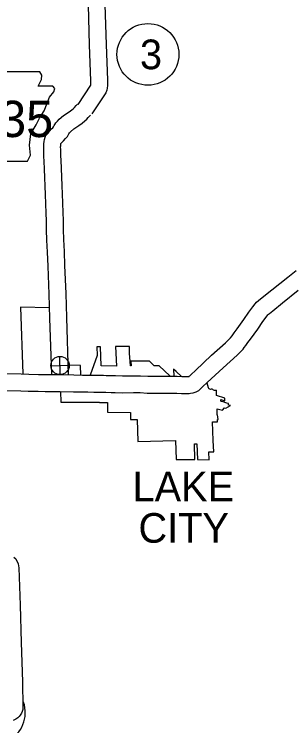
# Model space of a CAD drawing. Extents: x 1671357 to 13005564, y 567358 to 14261451.
# Drawn here: x 12758290.19 to 12758290.727, y 14259953.097 to 14259954.477 of the extents above; entities that cross this region are included whole.
import ezdxf

# ---------------------------------------------------------------- set-up
doc = ezdxf.new("R2010")
doc.units = 0
for name, color, linetype in [('10', 7, 'Continuous'), ('21', 7, 'Continuous'), ('24', 7, 'Continuous'), ('40', 7, 'Continuous'), ('6', 7, 'Continuous')]:
    doc.layers.add(name, color=color, linetype=linetype)

msp = doc.modelspace()

# ---------------------------------------------------------------- linework, layer by layer
at = {"layer": '10'}
for points in [[(12758290.3325, 14259954.4943), (12758290.335, 14259954.4173), (12758290.3373, 14259954.3478), (12758290.3375, 14259954.3426), (12758290.3374, 14259954.3404), (12758290.3373, 14259954.3392), (12758290.3127, 14259954.3018)], [(12758290.3652, 14259954.4953), (12758290.3676, 14259954.4183), (12758290.37, 14259954.3488), (12758290.3702, 14259954.3425), (12758290.37, 14259954.3383), (12758290.3696, 14259954.3334), (12758290.3687, 14259954.3293), (12758290.3667, 14259954.3244), (12758290.3399, 14259954.2838)], [(12758290.2622, 14259953.7782), (12758290.2587, 14259953.8875), (12758290.2574, 14259953.934), (12758290.2552, 14259953.9884), (12758290.2541, 14259954.0151), (12758290.253, 14259954.0389), (12758290.2524, 14259954.0585), (12758290.2522, 14259954.0761), (12758290.2517, 14259954.0911), (12758290.2503, 14259954.1272), (12758290.2497, 14259954.1431), (12758290.249, 14259954.1602), (12758290.2485, 14259954.1764), (12758290.2477, 14259954.1921), (12758290.2471, 14259954.2006), (12758290.247, 14259954.208), (12758290.247, 14259954.2136), (12758290.2468, 14259954.2195), (12758290.2469, 14259954.2223), (12758290.247, 14259954.2255), (12758290.2473, 14259954.23), (12758290.2481, 14259954.2341), (12758290.2494, 14259954.2381), (12758290.2517, 14259954.2433), (12758290.2557, 14259954.2481), (12758290.2583, 14259954.2508), (12758290.2619, 14259954.2543), (12758290.2644, 14259954.2568), (12758290.2657, 14259954.2585), (12758290.2671, 14259954.2608), (12758290.2682, 14259954.2629), (12758290.2701, 14259954.266), (12758290.2731, 14259954.2695), (12758290.2769, 14259954.273), (12758290.2852, 14259954.2802), (12758290.2959, 14259954.2876), (12758290.301, 14259954.2913), (12758290.3043, 14259954.2941), (12758290.3063, 14259954.2961), (12758290.3098, 14259954.2999), (12758290.3153, 14259954.3049)], [(12758290.2949, 14259953.7777), (12758290.2914, 14259953.8885), (12758290.29, 14259953.9351), (12758290.2878, 14259953.9898), (12758290.2867, 14259954.0165), (12758290.2857, 14259954.0401), (12758290.2851, 14259954.0592), (12758290.2849, 14259954.077), (12758290.2843, 14259954.0923), (12758290.2829, 14259954.1285), (12758290.2823, 14259954.1443), (12758290.2816, 14259954.1614), (12758290.2811, 14259954.1777), (12758290.2803, 14259954.1941), (12758290.2798, 14259954.2019), (12758290.2797, 14259954.2082), (12758290.2797, 14259954.2142), (12758290.2795, 14259954.2196), (12758290.2796, 14259954.2216), (12758290.2796, 14259954.224), (12758290.2797, 14259954.2256), (12758290.2797, 14259954.2258), (12758290.2798, 14259954.226), (12758290.2799, 14259954.2261), (12758290.2814, 14259954.2276), (12758290.2853, 14259954.2314), (12758290.2891, 14259954.2355), (12758290.2925, 14259954.2398), (12758290.2954, 14259954.2446), (12758290.2965, 14259954.2466), (12758290.2968, 14259954.2468), (12758290.2988, 14259954.2488), (12758290.3052, 14259954.2543), (12758290.3148, 14259954.2609), (12758290.3212, 14259954.2656), (12758290.3265, 14259954.2701), (12758290.33, 14259954.2736), (12758290.3328, 14259954.2767), (12758290.3373, 14259954.2808)], [(12758290.1697, 14259953.7798), (12758290.2032, 14259953.7791), (12758290.2178, 14259953.7787), (12758290.2365, 14259953.7781), (12758290.2496, 14259953.778), (12758290.2614, 14259953.7779), (12758290.2793, 14259953.7779), (12758290.3049, 14259953.7772), (12758290.322, 14259953.777), (12758290.3325, 14259953.7771), (12758290.3444, 14259953.7767), (12758290.3542, 14259953.7767), (12758290.3627, 14259953.7765), (12758290.3678, 14259953.7763), (12758290.3778, 14259953.7761), (12758290.3856, 14259953.776), (12758290.3993, 14259953.7753), (12758290.42, 14259953.7755), (12758290.434, 14259953.7755), (12758290.4483, 14259953.7748), (12758290.4571, 14259953.7747), (12758290.4686, 14259953.7747), (12758290.478, 14259953.7749), (12758290.5051, 14259953.7746), (12758290.5142, 14259953.7741), (12758290.524, 14259953.7741), (12758290.5262, 14259953.7741), (12758290.5278, 14259953.7743), (12758290.5279, 14259953.7743), (12758290.528, 14259953.7743), (12758290.5285, 14259953.7746), (12758290.5294, 14259953.7753), (12758290.5324, 14259953.7782), (12758290.5405, 14259953.7861), (12758290.5717, 14259953.8153), (12758290.5985, 14259953.8395), (12758290.606, 14259953.8468), (12758290.6075, 14259953.8483), (12758290.6083, 14259953.8495), (12758290.6112, 14259953.8533), (12758290.6152, 14259953.8592), (12758290.6209, 14259953.8666), (12758290.6344, 14259953.8845), (12758290.6439, 14259953.8992), (12758290.6512, 14259953.9095), (12758290.6559, 14259953.9151), (12758290.6587, 14259953.9182), (12758290.6628, 14259953.9219), (12758290.6697, 14259953.9272), (12758290.6885, 14259953.9423), (12758290.7191, 14259953.9671), (12758290.7357, 14259953.9801)], [(12758290.1691, 14259953.7471), (12758290.2025, 14259953.7465), (12758290.2169, 14259953.7461), (12758290.2358, 14259953.7455), (12758290.2493, 14259953.7453), (12758290.2613, 14259953.7452), (12758290.2788, 14259953.7452), (12758290.3044, 14259953.7445), (12758290.3219, 14259953.7444), (12758290.3321, 14259953.7444), (12758290.3439, 14259953.744), (12758290.3538, 14259953.7441), (12758290.3617, 14259953.7439), (12758290.3668, 14259953.7437), (12758290.3774, 14259953.7434), (12758290.3847, 14259953.7434), (12758290.3986, 14259953.7426), (12758290.4202, 14259953.7429), (12758290.4332, 14259953.7429), (12758290.4472, 14259953.7422), (12758290.4568, 14259953.742), (12758290.4689, 14259953.742), (12758290.4782, 14259953.7422), (12758290.5041, 14259953.7419), (12758290.5133, 14259953.7415), (12758290.5242, 14259953.7414), (12758290.528, 14259953.7415), (12758290.531, 14259953.7417), (12758290.5361, 14259953.7423), (12758290.542, 14259953.7447), (12758290.5469, 14259953.7473), (12758290.5511, 14259953.7509), (12758290.555, 14259953.7546), (12758290.5631, 14259953.7625), (12758290.5938, 14259953.7913), (12758290.6209, 14259953.8156), (12758290.629, 14259953.8235), (12758290.6326, 14259953.8272), (12758290.6348, 14259953.8302), (12758290.6379, 14259953.8344), (12758290.6417, 14259953.8401), (12758290.6469, 14259953.8468), (12758290.6613, 14259953.8658), (12758290.671, 14259953.8809), (12758290.6771, 14259953.8895), (12758290.6805, 14259953.8937), (12758290.6817, 14259953.8949), (12758290.6837, 14259953.8967), (12758290.69, 14259953.9016), (12758290.7091, 14259953.9169), (12758290.7395, 14259953.9415)], [(12758290.1886, 14259953.424), (12758290.1928, 14259953.4203), (12758290.1975, 14259953.4111), (12758290.1983, 14259953.403), (12758290.2008, 14259953.3307), (12758290.2033, 14259953.2583), (12758290.2055, 14259953.1822), (12758290.2064, 14259953.1331), (12758290.2061, 14259953.1285), (12758290.2047, 14259953.1243), (12758290.2034, 14259953.1211), (12758290.2011, 14259953.1173), (12758290.1989, 14259953.1148), (12758290.1965, 14259953.1124), (12758290.1928, 14259953.1099), (12758290.19, 14259953.1084), (12758290.1875, 14259953.1071)]]:
    msp.add_lwpolyline(points, dxfattribs=at)
at = {"layer": '21'}
msp.add_lwpolyline([(12758290.0737, 14259954.3649), (12758290.082, 14259954.3096), (12758290.0783, 14259954.2258), (12758290.0857, 14259954.2212), (12758290.0995, 14259954.2212), (12758290.0995, 14259954.1917), (12758290.2156, 14259954.1917), (12758290.2211, 14259954.2037), (12758290.2192, 14259954.223), (12758290.222, 14259954.2451), (12758290.2321, 14259954.2626), (12758290.2386, 14259954.2755), (12758290.2478, 14259954.2893), (12758290.2533, 14259954.3041), (12758290.2579, 14259954.3161), (12758290.2662, 14259954.3262), (12758290.2681, 14259954.3326), (12758290.2644, 14259954.3372), (12758290.2358, 14259954.3372), (12758290.2423, 14259954.3501), (12758290.2432, 14259954.3584), (12758290.2394, 14259954.3648)], close=True, dxfattribs=at)
at = {"layer": '24'}
msp.add_arc((12758290.1512, 14259953.1222), 0.0599, 294.8348, 20.097, dxfattribs=at)
at = {"layer": '40'}
for p, q in [((12758290.2787, 14259953.7778), (12758290.2779, 14259953.8132)), ((12758290.2606, 14259953.7951), (12758290.296, 14259953.7959))]:
    msp.add_line(p, q, dxfattribs=at)
for centre, radius in [((12758290.4484, 14259954.3989), 0.0599), ((12758290.2783, 14259953.7955), 0.0177)]:
    msp.add_circle(centre, radius, dxfattribs=at)
at = {"layer": '6'}
for points in [[(12758290.2581, 14259953.9076), (12758290.2018, 14259953.9084), (12758290.2063, 14259953.7791)], [(12758290.4703, 14259953.7946), (12758290.4603, 14259953.7946), (12758290.4516, 14259953.804), (12758290.4154, 14259953.8041), (12758290.4161, 14259953.7946), (12758290.4149, 14259953.7946), (12758290.4144, 14259953.7946), (12758290.4132, 14259953.8117), (12758290.413, 14259953.8187), (12758290.4126, 14259953.8275), (12758290.4125, 14259953.8322), (12758290.3857, 14259953.8327), (12758290.3877, 14259953.7945), (12758290.3582, 14259953.7946), (12758290.3568, 14259953.8316), (12758290.3496, 14259953.8317), (12758290.3499, 14259953.8149), (12758290.3364, 14259953.7769)], [(12758290.3183, 14259953.777), (12758290.3178, 14259953.7958), (12758290.2943, 14259953.7963)], [(12758290.4703, 14259953.7946), (12758290.4908, 14259953.7752)], [(12758290.4981, 14259953.7882), (12758290.4985, 14259953.7747)], [(12758290.5134, 14259953.7741), (12758290.5031, 14259953.7836), (12758290.4981, 14259953.7882)], [(12758290.5624, 14259953.7618), (12758290.5651, 14259953.7532), (12758290.5659, 14259953.7518), (12758290.5665, 14259953.751), (12758290.5675, 14259953.7502), (12758290.5686, 14259953.7499), (12758290.5694, 14259953.7498), (12758290.5712, 14259953.7501), (12758290.5723, 14259953.75), (12758290.5736, 14259953.7494), (12758290.575, 14259953.7486), (12758290.5766, 14259953.7479), (12758290.5789, 14259953.7475), (12758290.5809, 14259953.7475)], [(12758290.5745, 14259953.65), (12758290.5733, 14259953.6864), (12758290.5833, 14259953.6864), (12758290.5832, 14259953.6909), (12758290.5842, 14259953.6909), (12758290.5833, 14259953.7), (12758290.5827, 14259953.7), (12758290.5823, 14259953.7118), (12758290.5929, 14259953.7091), (12758290.5966, 14259953.7136), (12758290.5994, 14259953.7127), (12758290.6084, 14259953.7177), (12758290.6041, 14259953.7186), (12758290.6043, 14259953.7218), (12758290.6009, 14259953.7228), (12758290.5972, 14259953.724), (12758290.5941, 14259953.7251), (12758290.5907, 14259953.7259), (12758290.5893, 14259953.7266), (12758290.5893, 14259953.7296), (12758290.5971, 14259953.7273), (12758290.5971, 14259953.7323), (12758290.5813, 14259953.7376), (12758290.5809, 14259953.7475)], [(12758290.2793, 14259953.7452), (12758290.2796, 14259953.7247), (12758290.3546, 14259953.7245)], [(12758290.3546, 14259953.7245), (12758290.3546, 14259953.7239), (12758290.37, 14259953.7235), (12758290.3703, 14259953.705), (12758290.4144, 14259953.7047), (12758290.4148, 14259953.6906), (12758290.4276, 14259953.6906)], [(12758290.4276, 14259953.6906), (12758290.4287, 14259953.6481), (12758290.5017, 14259953.6501), (12758290.5028, 14259953.6135), (12758290.5395, 14259953.6134), (12758290.5386, 14259953.6436), (12758290.5433, 14259953.6435), (12758290.5445, 14259953.6133), (12758290.5667, 14259953.6128), (12758290.5663, 14259953.6279), (12758290.5758, 14259953.6279), (12758290.5745, 14259953.65)]]:
    msp.add_lwpolyline(points, dxfattribs=at)

# ---------------------------------------------------------------- texts
at = {"layer": '21'}
msp.add_text('135', height=0.07044, dxfattribs=at).set_placement((12758290.1079, 14259954.2386))
at = {"layer": '40'}
msp.add_text('3', height=0.0575, dxfattribs=at).set_placement((12758290.433, 14259954.3702))
at = {"layer": '6'}
for s, p in [('LAKE', (12758290.4187, 14259953.532)), ('CITY', (12758290.4301, 14259953.4518))]:
    msp.add_text(s, height=0.0575, dxfattribs=at).set_placement(p)

doc.saveas('drawing.dxf')
